Omron CX-Programmer project NewProject (CX-Programmer 9.42)

# PLC NewPLC1: CP1L-E EM

## Program NewProgram1 (cyclic task 0)

### Section Section1

### Section END
; rung 0
END(001)

# PLC NewPLC2: CP1L-E EM

## Program NewProgram1 (cyclic task 0)

### Section Section1

### Section END
; rung 0
END(001)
